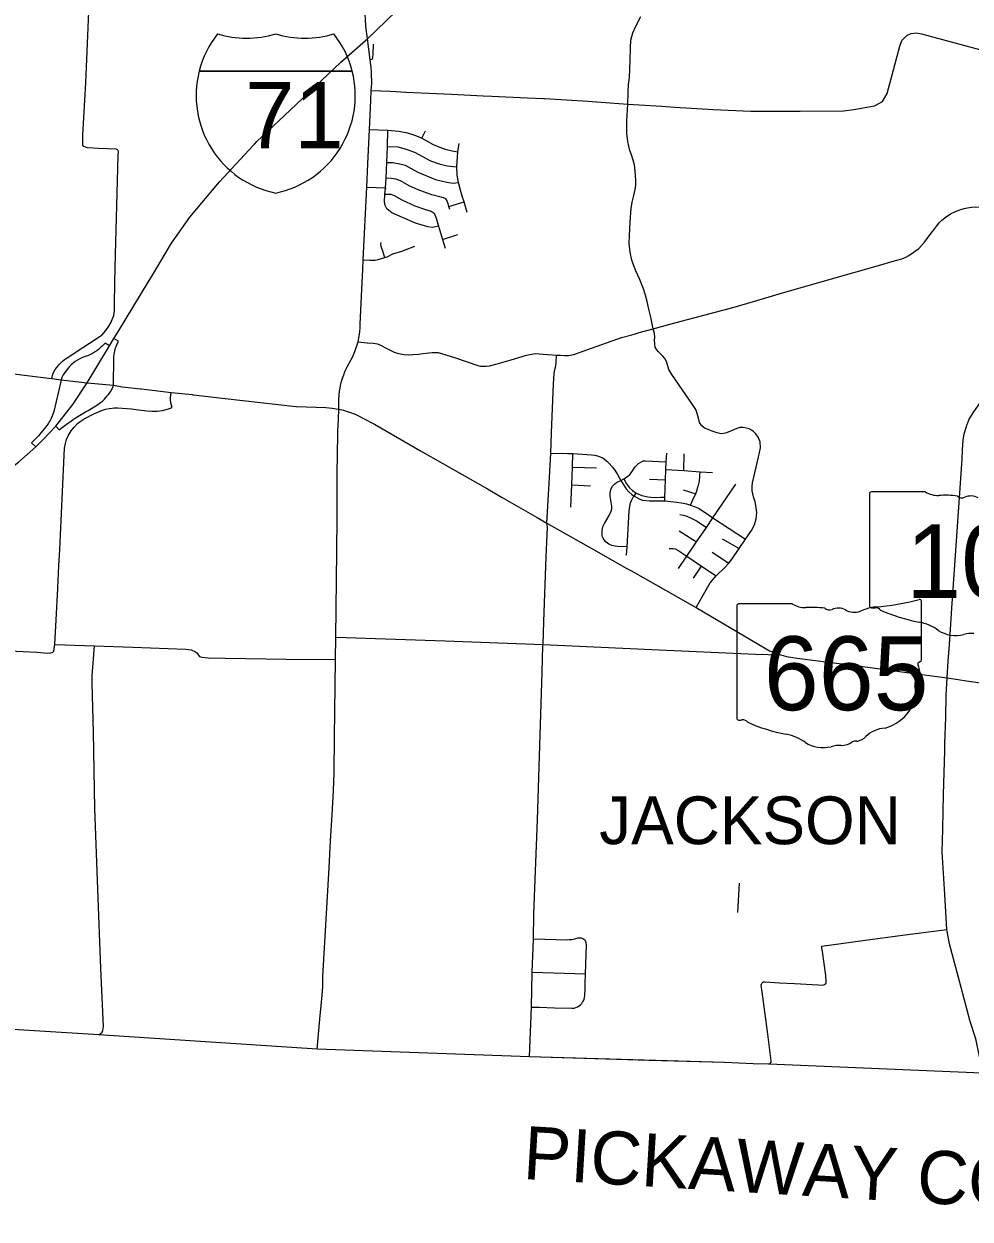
# Model space of a CAD drawing. Extents: x 1755200 to 1902939, y 644115 to 788070.
# Drawn here: x 1801507 to 1819343, y 655078 to 677595 of the extents above; entities that cross this region are included whole.
import ezdxf

# ---------------------------------------------------------------- set-up
doc = ezdxf.new("R2010")
doc.units = 0
for name, color, linetype in [('GM_X_Adjacent_County_Text', 7, 'Continuous'), ('GM_X_City_Street', 7, 'Continuous'), ('GM_X_County', 7, 'Continuous'), ('GM_X_County_Road', 7, 'Continuous'), ('GM_X_Interchange_Ramps', 7, 'Continuous'), ('GM_X_Interstate_Route', 7, 'Continuous'), ('GM_X_Interstate_Shield', 7, 'Continuous'), ('GM_X_State_Route', 7, 'Continuous'), ('GM_X_State_Shield', 7, 'Continuous'), ('GM_X_Township_Road', 7, 'Continuous'), ('GM_X_Township_Text', 7, 'Continuous')]:
    doc.layers.add(name, color=color, linetype=linetype)

msp = doc.modelspace()

# ---------------------------------------------------------------- linework, layer by layer
at = {"layer": 'GM_X_City_Street'}
for points in [[(1813371, 671853), (1813325, 672068), (1813288, 672219), (1813255, 672367), (1813224, 672487), (1813186, 672606), (1813109, 672790), (1813036, 672955), (1812989, 673072), (1812967, 673143), (1812934, 673292), (1812918, 673466), (1812919, 673605), (1812936, 673864), (1812955, 674114), (1812972, 674238), (1813004, 674362), (1813030, 674473), (1813041, 674557), (1813043, 674649), (1813032, 674821), (1813016, 674937), (1812991, 675029), (1812959, 675131), (1812930, 675207), (1812908, 675291), (1812891, 675379), (1812874, 675536), (1812874, 675771), (1812889, 676084), (1812895, 676306), (1812902, 676452), (1812924, 676588), (1812932, 676903), (1812940, 677144), (1812948, 677290), (1812987, 677426), (1813041, 677549), (1813136, 677735)], [(1808058, 676402), (1808063, 676477), (1808063, 676539), (1808061, 676598), (1808058, 676692), (1808050, 676769)], [(1807444, 670339), (1807443, 670385), (1807445, 670514), (1807450, 670604), (1807457, 670674), (1807466, 670730), (1807476, 670782), (1807495, 670864), (1807513, 670923), (1807536, 670984), (1807556, 671037), (1807578, 671084), (1807603, 671137), (1807669, 671259), (1807706, 671327), (1807747, 671422), (1807808, 671602), (1807828, 671710), (1807837, 671791), (1807844, 671870), (1807847, 671938), (1807871, 672467), (1807895, 672976), (1807904, 673151), (1807971, 674520), (1807990, 674960), (1808022, 675604), (1808045, 676151), (1808054, 676341), (1808058, 676402)], [(1810161, 676241), (1810328, 676234), (1810996, 676200), (1811302, 676188), (1811320, 676187)], [(1811320, 676187), (1812139, 676140), (1812889, 676084), (1813531, 676044)], [(1808022, 675604), (1808366, 675591), (1808575, 675576), (1808735, 675543), (1808910, 675486), (1809010, 675439), (1809062, 675412), (1809120, 675379), (1809222, 675322), (1809299, 675291), (1809446, 675234), (1809581, 675206), (1809685, 675186)], [(1809319, 673783), (1809217, 673762), (1809118, 673771), (1808890, 673840), (1808445, 674038), (1808346, 674111), (1808316, 674174), (1808304, 674240), (1808313, 674387), (1808320, 674504), (1808333, 674689), (1808346, 674982), (1808358, 675288), (1808366, 675591)], [(1809010, 675439), (1809075, 675579)], [(1808358, 675288), (1808556, 675277), (1808712, 675237), (1808872, 675180), (1809020, 675094), (1809169, 675018), (1809337, 674958), (1809485, 674919), (1809666, 674902)], [(1809865, 674044), (1809840, 674131), (1809805, 674245), (1809774, 674332), (1809735, 674464), (1809700, 674604), (1809676, 674744), (1809666, 674902), (1809685, 675186), (1809710, 675342)], [(1808346, 674982), (1808463, 674982), (1808595, 674961), (1808694, 674931), (1808932, 674802), (1809266, 674664), (1809481, 674615), (1809599, 674595), (1809700, 674604)], [(1809535, 674098), (1809515, 674156), (1809503, 674206), (1809478, 674275), (1809458, 674298), (1809419, 674317), (1809347, 674335), (1809197, 674376), (1808936, 674467), (1808767, 674546), (1808607, 674639), (1808520, 674670), (1808427, 674682), (1808333, 674689)], [(1807971, 674520), (1808320, 674504), (1808322, 674482)], [(1808313, 674387), (1808421, 674384), (1808487, 674360), (1808628, 674282), (1808875, 674168), (1809061, 674102), (1809181, 674068), (1809238, 674032), (1809277, 673933), (1809319, 673783), (1809397, 673533), (1809449, 673368)], [(1809515, 674156), (1809805, 674245)], [(1808311, 673195), (1808268, 673330), (1808256, 673366), (1808243, 673405), (1808236, 673441), (1808242, 673477)], [(1809397, 673533), (1809684, 673627)], [(1807904, 673151), (1808030, 673144), (1808128, 673144), (1808183, 673156), (1808311, 673195), (1808356, 673208), (1808464, 673260), (1808633, 673312), (1808874, 673405)], [(1803152, 671978), (1803161, 671994), (1803199, 672099), (1803215, 672193), (1803215, 672321), (1803217, 672421), (1803219, 672602)], [(1812964, 671740), (1813007, 671752), (1813102, 671780), (1813371, 671853)], [(1813371, 671853), (1813524, 671895)], [(1814180, 666603), (1814291, 666801), (1814442, 667062), (1814554, 667195), (1814727, 667360), (1814796, 667438), (1814856, 667514), (1814989, 667712), (1815107, 667885), (1815223, 668049), (1815281, 668158), (1815311, 668272), (1815321, 668387), (1815311, 668487), (1815289, 668592), (1815259, 668688), (1815237, 668800), (1815234, 668881), (1815241, 668947), (1815354, 669430), (1815390, 669609), (1815383, 669721), (1815349, 669811), (1815305, 669869), (1815256, 669921), (1815219, 669941), (1815178, 669963), (1815121, 669980), (1815066, 669988), (1815004, 669988), (1814945, 669974), (1814816, 669918), (1814732, 669884), (1814651, 669874), (1814577, 669890), (1814463, 669931), (1814403, 669953), (1814338, 669980), (1814285, 670023), (1814242, 670088), (1814220, 670164), (1814197, 670252), (1814172, 670328), (1814054, 670505), (1813719, 670987), (1813666, 671083), (1813620, 671234), (1813586, 671292), (1813549, 671336), (1813470, 671416), (1813437, 671455), (1813409, 671506), (1813398, 671565), (1813394, 671634), (1813398, 671695), (1813394, 671765), (1813371, 671853)], [(1807808, 671602), (1807979, 671589), (1808089, 671579), (1808169, 671566), (1808239, 671539), (1808334, 671486), (1808411, 671446), (1808488, 671411), (1808569, 671388), (1808676, 671368), (1808763, 671360), (1808837, 671364), (1808943, 671373), (1809033, 671384), (1809138, 671400), (1809200, 671405), (1809249, 671406), (1809313, 671401), (1809378, 671387), (1809640, 671306), (1810062, 671158), (1810111, 671149), (1810165, 671145), (1810219, 671145), (1810281, 671154), (1810427, 671193), (1810689, 671267), (1810983, 671351), (1811142, 671387), (1811295, 671373), (1811548, 671356)], [(1802144, 666960), (1802145, 666972), (1802166, 667386), (1802182, 667694), (1802275, 669603), (1802288, 669690), (1802309, 669763), (1802341, 669832), (1802395, 669929), (1802452, 669999), (1802515, 670066), (1802567, 670104), (1802645, 670155), (1802822, 670246), (1802901, 670283), (1802971, 670312), (1803047, 670335), (1803115, 670349), (1803170, 670356), (1803217, 670360), (1803279, 670363), (1803356, 670358), (1803538, 670341), (1803665, 670325), (1803822, 670306), (1803921, 670298), (1804021, 670301), (1804122, 670312), (1804188, 670328), (1804254, 670350), (1804301, 670368), (1804277, 670456), (1804270, 670510), (1804273, 670557), (1804284, 670651)], [(1807426, 669861), (1807427, 669920), (1807436, 670149), (1807444, 670339)], [(1811438, 669509), (1811752, 669502)], [(1811752, 669502), (1811856, 669500), (1812119, 669485), (1812205, 669479), (1812270, 669471), (1812338, 669454), (1812414, 669418), (1812445, 669399), (1812492, 669359), (1812538, 669315), (1812595, 669248), (1812644, 669186), (1812693, 669108), (1812757, 668992), (1812820, 668894), (1812861, 668838), (1812911, 668777), (1812969, 668731), (1813010, 668700), (1813021, 668691), (1813117, 668638), (1813169, 668624), (1813298, 668612), (1813586, 668612), (1813700, 668595), (1813807, 668582), (1813905, 668570), (1813994, 668554), (1814072, 668528), (1814161, 668495), (1814222, 668470), (1814293, 668425), (1814427, 668331), (1814493, 668288), (1815107, 667885)], [(1811816, 668488), (1811834, 668910), (1811848, 669242), (1811856, 669500)], [(1813586, 668612), (1813589, 668680), (1813602, 669006), (1813610, 669198), (1813616, 669346), (1813623, 669508)], [(1813949, 669178), (1813954, 669498)], [(1811848, 669242), (1812300, 669229)], [(1812757, 668992), (1812816, 669026), (1812887, 669067), (1812927, 669104), (1812956, 669136), (1813031, 669249), (1813059, 669284), (1813094, 669315), (1813133, 669339), (1813180, 669361), (1813226, 669361), (1813616, 669346)], [(1813610, 669198), (1813949, 669178), (1814252, 669159), (1814484, 669145)], [(1812877, 667743), (1812699, 667748), (1812649, 667754), (1812586, 667771), (1812533, 667796), (1812482, 667830), (1812444, 667872), (1812423, 667905), (1812409, 667947), (1812405, 667985), (1812407, 668042), (1812420, 668117), (1812449, 668184), (1812536, 668335), (1812575, 668413), (1812589, 668459), (1812587, 668511), (1812572, 668620), (1812559, 668698), (1812558, 668757), (1812564, 668800), (1812579, 668840), (1812603, 668885), (1812643, 668927), (1812680, 668954), (1812757, 668992)], [(1812816, 669026), (1812866, 668932), (1812922, 668857), (1812978, 668807), (1813049, 668755), (1813064, 668745), (1813154, 668709), (1813269, 668682), (1813389, 668673), (1813511, 668677), (1813589, 668680)], [(1813298, 669019), (1813602, 669006)], [(1814072, 668528), (1814142, 668682), (1814165, 668727), (1814171, 668743), (1814197, 668816), (1814212, 668872), (1814221, 668901), (1814239, 668985), (1814252, 669159)], [(1811834, 668910), (1812186, 668895)], [(1812868, 667589), (1812877, 667743), (1812917, 668416), (1812927, 668506), (1812942, 668574), (1812967, 668631), (1812993, 668676), (1813010, 668700), (1813049, 668755)], [(1813931, 668818), (1814171, 668743)], [(1814493, 668288), (1814928, 668921)], [(1813871, 668355), (1813943, 668342), (1814004, 668319), (1814086, 668284), (1814200, 668225), (1814371, 668107)], [(1813846, 667336), (1814002, 667566), (1814186, 667836), (1814371, 668107), (1814493, 668288)], [(1813858, 668045), (1814186, 667836)], [(1814668, 667896), (1814989, 667712)], [(1813672, 667714), (1813716, 667712), (1813746, 667711), (1813781, 667706), (1813852, 667667), (1814002, 667566), (1814278, 667381), (1814554, 667195)], [(1814481, 667641), (1814796, 667438)], [(1814126, 667154), (1814278, 667381)]]:
    msp.add_lwpolyline(points, dxfattribs=at)
at = {"layer": 'GM_X_County'}
msp.add_lwpolyline([(1819565, 657827), (1815551, 657995), (1815251, 658006), (1814713, 658027), (1811039, 658133), (1807036, 658278), (1802918, 658549), (1799575, 658756), (1799409, 658764), (1794213, 659039), (1792928, 659077), (1789408, 659196), (1786100, 659304), (1784956, 659328), (1781576, 659434)], dxfattribs=at)
at = {"layer": 'GM_X_County_Road'}
for points in [[(1803219, 672602), (1803221, 672730), (1803234, 673250), (1803272, 674640), (1803283, 675115), (1803288, 675187), (1803285, 675207), (1803273, 675221), (1803245, 675232), (1802913, 675248), (1802703, 675262), (1802634, 675285), (1802620, 675312), (1802618, 675506), (1802675, 676484), (1802712, 677379), (1802738, 677978)], [(1808050, 676769), (1808035, 676927), (1807985, 677316), (1807955, 677555), (1807945, 677686), (1807941, 677769), (1807951, 677851), (1807966, 677926), (1807968, 677930)], [(1813531, 676044), (1813778, 676029), (1814498, 675982), (1815209, 675949), (1815732, 675949), (1816142, 675951), (1816958, 675960), (1817150, 675979), (1817539, 676052), (1817692, 676132), (1817778, 676281), (1818016, 677175), (1818058, 677282), (1818149, 677378), (1818232, 677416), (1818323, 677425), (1818424, 677407), (1819616, 677087), (1819830, 677029)], [(1808054, 676341), (1808419, 676325), (1808703, 676311), (1809140, 676287), (1809565, 676268), (1810161, 676241)], [(1802031, 670914), (1802043, 670971), (1802059, 671014), (1802099, 671084), (1802125, 671124), (1802165, 671170), (1802235, 671239), (1802292, 671283), (1802355, 671323), (1802495, 671415), (1802744, 671577), (1802982, 671739), (1803052, 671816), (1803108, 671902), (1803152, 671978)], [(1807380, 665621), (1807386, 666038), (1807393, 666575), (1807406, 667664), (1807413, 668280), (1807413, 669117), (1807426, 669857), (1807426, 669861)], [(1802087, 665905), (1802116, 666365), (1802144, 666960)], [(1795747, 666045), (1796176, 666025), (1797552, 665961), (1799023, 665886), (1800577, 665809), (1801360, 665776), (1801750, 665758), (1801954, 665741), (1802014, 665745), (1802050, 665761), (1802068, 665780), (1802080, 665822), (1802087, 665905)], [(1807036, 658278), (1807084, 658842), (1807119, 659163), (1807132, 659294), (1807140, 659461), (1807143, 659649), (1807258, 661693), (1807288, 662202), (1807315, 662693), (1807343, 663154), (1807353, 663488), (1807361, 664158), (1807373, 665125), (1807380, 665621)]]:
    msp.add_lwpolyline(points, dxfattribs=at)
at = {"layer": 'GM_X_Interchange_Ramps'}
for points in [[(1803122, 671531), (1803036, 671583), (1802983, 671525), (1802952, 671496), (1802918, 671466), (1802879, 671437), (1802835, 671408), (1802799, 671387), (1802761, 671368), (1802722, 671350), (1802681, 671335), (1802644, 671322), (1802600, 671305), (1802561, 671286), (1802517, 671262), (1802475, 671235), (1802436, 671205), (1802398, 671171), (1802366, 671138), (1802335, 671103), (1802302, 671058), (1802278, 671030), (1802247, 670984), (1802219, 670935), (1802208, 670890)], [(1803193, 670787), (1803195, 670832), (1803199, 671255), (1803200, 671299), (1803203, 671335), (1803206, 671365), (1803212, 671401), (1803218, 671431), (1803226, 671461), (1803235, 671490), (1803246, 671520), (1803258, 671550), (1803288, 671617), (1803204, 671668)], [(1802208, 670890), (1802204, 670858), (1802071, 670292), (1802059, 670255), (1802048, 670224), (1802034, 670189), (1802015, 670150), (1802000, 670121), (1801985, 670096), (1801972, 670075), (1801956, 670052), (1801940, 670030), (1801783, 669834), (1801653, 669700), (1801729, 669625)], [(1802106, 670017), (1802174, 669949), (1802228, 669991), (1802276, 670028), (1802331, 670069), (1802382, 670104), (1802434, 670140), (1802489, 670177), (1802556, 670219), (1802616, 670255), (1802667, 670285), (1802717, 670313), (1802831, 670382), (1802903, 670424), (1802951, 670459), (1802987, 670489), (1803024, 670525), (1803054, 670556), (1803079, 670586), (1803102, 670615), (1803147, 670676), (1803190, 670756), (1803193, 670787)]]:
    msp.add_lwpolyline(points, dxfattribs=at)
at = {"layer": 'GM_X_Interstate_Route'}
for points in [[(1807945, 677280), (1807985, 677316), (1809229, 678516), (1809777, 678981), (1810555, 679722), (1810785, 679939)], [(1805829, 675306), (1805854, 675332), (1805897, 675379), (1806633, 676072), (1807481, 676871), (1807944, 677280), (1807945, 677280)], [(1803929, 672859), (1804291, 673463), (1804633, 673955), (1805195, 674617), (1805829, 675306)], [(1803288, 671806), (1803851, 672729), (1803929, 672859)], [(1802697, 670834), (1803122, 671531), (1803204, 671668), (1803288, 671806)], [(1801226, 669208), (1801405, 669341), (1801729, 669625), (1801864, 669759), (1802106, 670017), (1802426, 670424), (1802697, 670834)]]:
    msp.add_lwpolyline(points, dxfattribs=at)
at = {"layer": 'GM_X_Interstate_Shield'}
for p, q in [((1804810, 676704), (1807696, 676704)), ((1807696, 676704), (1804810, 676704)), ((1807696, 676704), (1804810, 676704))]:
    msp.add_line(p, q, dxfattribs=at)
for centre, start, end in [((1806628, 676245), 141.669, 165.8066), ((1805705, 679201), 253.0091, 286.9909), ((1806801, 679201), 253.0091, 286.9909), ((1805878, 676245), 14.1934, 38.331), ((1806628, 676245), 165.8066, 258.463), ((1805878, 676245), 281.537, 14.1934)]:
    msp.add_arc(centre, 1875, start, end, dxfattribs=at)
at = {"layer": 'GM_X_State_Route'}
for points in [[(1794757, 671777), (1794806, 671771), (1797266, 671486), (1797804, 671424), (1799105, 671270), (1800498, 671103), (1801820, 670938), (1801979, 670920)], [(1819288, 670053), (1819297, 670077), (1819327, 670145), (1819411, 670285), (1819487, 670390), (1819563, 670503), (1819691, 670679), (1819757, 670808), (1819851, 671000), (1819892, 671158), (1819910, 671407), (1819904, 671713), (1819894, 671894)], [(1801979, 670920), (1802031, 670914), (1802164, 670896)], [(1802164, 670896), (1802208, 670890), (1802697, 670834), (1803193, 670787), (1803359, 670760)], [(1803359, 670760), (1803705, 670721), (1803721, 670719)], [(1803721, 670719), (1804134, 670670)], [(1804134, 670670), (1804284, 670651), (1804289, 670651)], [(1804289, 670651), (1804678, 670611), (1804699, 670609), (1804702, 670608)], [(1804702, 670608), (1805301, 670538), (1806630, 670385), (1806646, 670384), (1807196, 670367), (1807318, 670355), (1807392, 670345)], [(1807392, 670345), (1807444, 670339), (1807531, 670315), (1807601, 670294), (1807661, 670275), (1807730, 670249), (1807777, 670228), (1807935, 670145)], [(1807935, 670145), (1808076, 670072)], [(1808076, 670072), (1808114, 670051), (1808982, 669552), (1810244, 668838), (1810520, 668670), (1811183, 668298), (1811362, 668191), (1812385, 667611), (1812857, 667344)], [(1819017, 666852), (1819017, 666860), (1819192, 669395), (1819197, 669568), (1819211, 669750), (1819230, 669872), (1819266, 669993), (1819288, 670053)], [(1812857, 667344), (1812945, 667295)], [(1812945, 667295), (1814068, 666660), (1814180, 666603), (1815498, 665821), (1815564, 665785), (1815626, 665766), (1815698, 665736), (1815770, 665711), (1815820, 665697), (1815821, 665697)], [(1818999, 666589), (1818999, 666596), (1819017, 666852)], [(1818991, 666483), (1818999, 666589)], [(1818951, 665904), (1818991, 666483)], [(1818929, 665588), (1818951, 665904)], [(1815821, 665697), (1815880, 665680), (1816082, 665646), (1816726, 665563), (1817285, 665493)], [(1817285, 665493), (1817287, 665493), (1817319, 665489), (1818151, 665376), (1818908, 665272)], [(1818908, 665272), (1818929, 665588)], [(1818882, 664535), (1818893, 664950), (1818908, 665272)], [(1818908, 665272), (1819117, 665243)], [(1819117, 665243), (1819273, 665220)], [(1819273, 665220), (1819666, 665165), (1820737, 665022)], [(1818865, 663903), (1818869, 664029), (1818882, 664535)], [(1819565, 657827), (1819530, 658083), (1819453, 658477), (1819341, 658803), (1819173, 659438), (1818957, 660262), (1818902, 660536), (1818866, 661195), (1818818, 661994), (1818827, 662427), (1818840, 663079), (1818865, 663897), (1818865, 663903)]]:
    msp.add_lwpolyline(points, dxfattribs=at)
at = {"layer": 'GM_X_State_Shield'}
for p, q in [((1818501, 668778), (1817481, 668778)), ((1817447, 668741), (1817447, 666628)), ((1814944, 666629), (1814944, 664516)), ((1815997, 666666), (1814978, 666666)), ((1818424, 665613), (1818424, 666718)), ((1818424, 665613), (1818424, 665613))]:
    msp.add_line(p, q, dxfattribs=at)
for centre, major_axis, start_param, end_param in [((1817487, 668746), (40.3, 0), 1.712693, 3.28349), ((1818743, 669023), (391, 0), 4.042523, 4.731795), ((1818873, 667591), (1404, 0), 1.404758, 1.657858), ((1819192, 668757), (113, 0), 3.836095, 5.185415), ((1819357, 668513), (235, 0), 0.950623, 2.079405), ((1817184, 669547), (3691, 0), 4.814394, 5.042369), ((1818385, 666723), (38.7, 0), 6.141152, 7.989035), ((1814983, 666634), (40.3, 0), 1.712693, 3.28349), ((1816240, 666911), (391, 0), 4.042523, 4.731795), ((1816369, 665479), (1404, 0), 1.404758, 1.657858), ((1816688, 666645), (113, 0), 3.836095, 5.185415), ((1816854, 666401), (235, 0), 0.950623, 2.079405), ((1817157, 666736), (282, 0), 4.081561, 5.145723), ((1817655, 666020), (743, 0), 1.699011, 2.107814), ((1817487, 666624), (40.7, 0), 3.00124, 4.508301), ((1817494, 666840), (310, 0), 4.665946, 4.897461), ((1817557, 666506), (112, 0), 0.519207, 1.627899), ((1818970, 668405), (2665, 0), 4.195997, 4.488961), ((1818176, 665679), (834, 0), 0.823519, 1.323587), ((1819078, 666496), (529, 0), 4.026481, 4.996735), ((1819383, 665765), (435, 0), 1.495662, 1.94098), ((1818383, 665608), (41.5, 0), 5.05454, 6.418171), ((1818415, 665532), (60, 0), 1.883978, 3.671073), ((1818033, 665392), (360, 0), 5.934695, 6.695948), ((1818563, 665150), (262, 0), 2.387724, 3.262537), ((1817391, 665009), (923, 0), 5.101752, 6.440018), ((1814984, 664512), (40.7, 0), 3.00124, 4.508301), ((1814990, 664728), (310, 0), 4.665946, 4.897461), ((1815053, 664394), (112, 0), 0.519207, 1.627899), ((1816467, 666293), (2665, 0), 4.195997, 4.488961), ((1817780, 663923), (506, 0), 1.647645, 2.488434), ((1815672, 663567), (834, 0), 0.823519, 1.323587), ((1816574, 664384), (529, 0), 4.026481, 4.996735), ((1816918, 664226), (282, 0), 4.691044, 5.507374), ((1817173, 664021), (79.4, 0), 1.147584, 2.315152), ((1817140, 664311), (298, 0), 4.937069, 5.64225), ((1816880, 663653), (435, 0), 1.495662, 1.94098)]:
    msp.add_ellipse(centre, major_axis=major_axis, ratio=0.8, start_param=start_param, end_param=end_param, dxfattribs=at)
at = {"layer": 'GM_X_Township_Road'}
for points in [[(1808035, 676927), (1808076, 676932), (1808083, 676964), (1808089, 677022), (1808098, 677210)], [(1818639, 673691), (1818713, 673791), (1818758, 673849), (1818811, 673898), (1818889, 673962), (1818974, 674019), (1819078, 674068), (1819165, 674100), (1819229, 674119), (1819292, 674130), (1819370, 674141), (1819453, 674147), (1819543, 674139), (1819631, 674125), (1819799, 674090), (1820046, 674039), (1820110, 674036)], [(1815261, 672367), (1815745, 672507), (1816597, 672757), (1817701, 673069), (1817865, 673116), (1818057, 673170), (1818129, 673198), (1818188, 673231), (1818270, 673290), (1818376, 673366), (1818429, 673417), (1818483, 673483), (1818628, 673677), (1818639, 673691)], [(1813524, 671895), (1813800, 671971), (1814892, 672260), (1815261, 672367)], [(1811548, 671356), (1811623, 671352), (1811696, 671349), (1811744, 671348), (1811771, 671349), (1811803, 671353), (1811838, 671360), (1811871, 671368), (1812121, 671456), (1812771, 671685), (1812964, 671740)], [(1811362, 668191), (1811416, 669051), (1811438, 669509), (1811451, 669891), (1811487, 670815), (1811500, 671008), (1811506, 671050), (1811514, 671082), (1811527, 671127), (1811533, 671154), (1811541, 671218), (1811548, 671356)], [(1811291, 665875), (1811292, 665901), (1811306, 666338), (1811353, 667557), (1811374, 668115), (1811362, 668191)], [(1802087, 665905), (1802839, 665876), (1803558, 665850), (1804556, 665817), (1804662, 665801), (1804741, 665764), (1804773, 665741), (1804794, 665709), (1804818, 665674), (1804862, 665665), (1804980, 665653), (1805300, 665647), (1806455, 665628), (1807380, 665621)], [(1802918, 658549), (1802980, 658597), (1802995, 658634), (1803006, 658708), (1802958, 659796), (1802900, 661294), (1802846, 662815), (1802821, 664254), (1802796, 665173), (1802793, 665313), (1802839, 665876)], [(1807386, 666038), (1809447, 665969), (1811292, 665901), (1813340, 665809), (1815297, 665721), (1815770, 665711)], [(1811039, 658133), (1811072, 659073), (1811090, 659728), (1811110, 660352), (1811119, 660831), (1811186, 662602), (1811227, 663802), (1811276, 665382), (1811291, 665875)], [(1814965, 660853), (1814995, 661407)], [(1815551, 657995), (1815575, 658012), (1815590, 658037), (1815593, 658057), (1815581, 658160), (1815528, 658564), (1815420, 659358), (1815404, 659486), (1815408, 659507), (1815420, 659527), (1815433, 659540), (1815450, 659546), (1815480, 659550), (1815748, 659532), (1816032, 659517), (1816480, 659491), (1816558, 659488), (1816595, 659497), (1816630, 659521), (1816631, 659549), (1816626, 659670), (1816562, 660118), (1816549, 660179), (1816546, 660222), (1817320, 660326), (1818070, 660426), (1818902, 660536)], [(1811072, 659073), (1811223, 659069), (1811508, 659060), (1811835, 659050), (1811856, 659050), (1811881, 659054), (1811913, 659062), (1811942, 659075), (1811971, 659093), (1811999, 659117), (1812021, 659140), (1812038, 659162), (1812052, 659187), (1812066, 659220), (1812076, 659255), (1812081, 659284), (1812085, 659415), (1812089, 659509), (1812095, 659700), (1812111, 660245), (1812107, 660281), (1812101, 660300), (1812091, 660318), (1812078, 660333), (1812064, 660347), (1812047, 660359), (1812032, 660366), (1812017, 660371), (1812000, 660373), (1811976, 660373), (1811951, 660370), (1811922, 660362), (1811883, 660350), (1811832, 660340), (1811807, 660336), (1811783, 660336), (1811752, 660335), (1811110, 660352)], [(1811090, 659728), (1812095, 659700)], [(1813295, 658068), (1811039, 658133)], [(1815551, 657995), (1815251, 658006), (1814713, 658027), (1813295, 658068)]]:
    msp.add_lwpolyline(points, dxfattribs=at)

# ---------------------------------------------------------------- texts
at = {"layer": 'GM_X_Adjacent_County_Text'}
msp.add_text('PICKAWAY COUNTY', height=1000, rotation=356.5821, dxfattribs=at).set_placement((1810900, 655835))
at = {"layer": 'GM_X_Interstate_Shield'}
msp.add_text('71', height=1250, dxfattribs=at).set_placement((1805676, 675251))
at = {"layer": 'GM_X_State_Shield'}
for s, p in [('104', (1818139, 666777)), ('665', (1815454, 664665))]:
    msp.add_text(s, height=1392.2, dxfattribs=at).set_placement(p)
at = {"layer": 'GM_X_Township_Text'}
msp.add_text('JACKSON', height=900, rotation=0, dxfattribs=at).set_placement((1812351, 662141))

doc.saveas('drawing.dxf')
